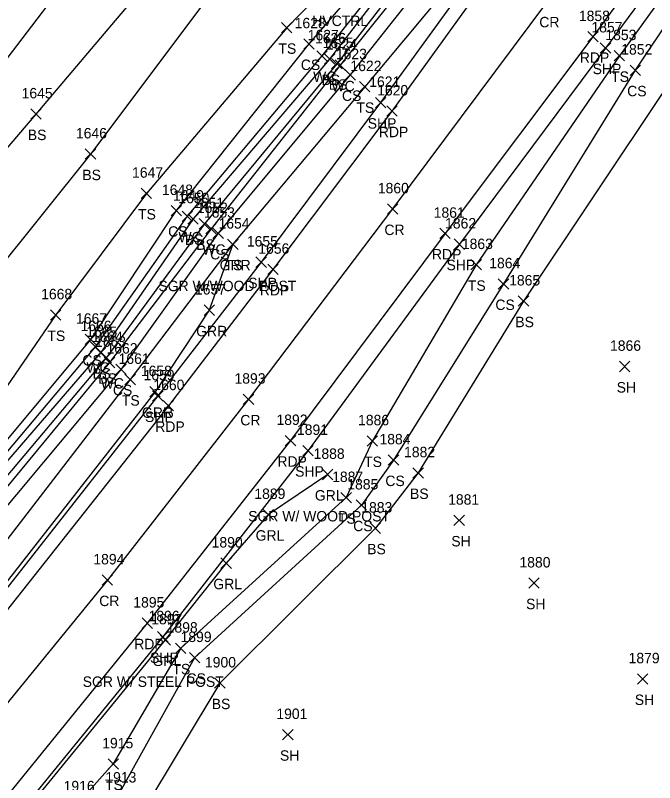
# Model space of a CAD drawing. Extents: x 1520648 to 1523413, y 732854 to 735518.
# Drawn here: x 1522267.9 to 1522390.5, y 733961.6 to 734108.7 of the extents above; entities that cross this region are included whole.
import ezdxf

# ---------------------------------------------------------------- set-up
doc = ezdxf.new("R2010")
doc.units = 0
for name, color, linetype in [('C_A', 7, 'Continuous'), ('D_I', 7, 'Continuous'), ('L_A', 7, 'Continuous'), ('L_I', 7, 'Continuous'), ('L_TIC', 7, 'Continuous'), ('LAWE', 7, 'Continuous'), ('LELB', 7, 'Continuous'), ('P_A', 7, 'Continuous'), ('P_I', 7, 'Continuous'), ('P_TIC', 7, 'Continuous'), ('PET', 7, 'Continuous'), ('PRC', 7, 'Continuous'), ('PSP', 7, 'Continuous'), ('R_A', 7, 'Continuous'), ('R_C', 7, 'Continuous'), ('R_I', 7, 'Continuous'), ('R_TIC', 7, 'Continuous'), ('RGR', 7, 'Continuous')]:
    doc.layers.add(name, color=color, linetype=linetype)

msp = doc.modelspace()

# ---------------------------------------------------------------- linework, layer by layer
at = {"layer": 'L_TIC'}
for points in [[(1522318.92, 734105.37), (1522320.92, 734107.37)], [(1522320.92, 734105.37), (1522318.92, 734107.37)], [(1522323.18, 734102.26), (1522325.18, 734104.26)], [(1522325.18, 734102.26), (1522323.18, 734104.26)], [(1522325.68, 734099.96), (1522327.68, 734101.96)], [(1522327.68, 734099.96), (1522325.68, 734101.96)], [(1522382.71, 734099.99), (1522384.71, 734101.99)], [(1522384.71, 734099.99), (1522382.71, 734101.99)], [(1522327.14, 734099.37), (1522329.14, 734101.37)], [(1522329.14, 734099.37), (1522327.14, 734101.37)], [(1522328.53, 734098.47), (1522330.53, 734100.47)], [(1522330.53, 734098.47), (1522328.53, 734100.47)], [(1522329.19, 734098.19), (1522331.19, 734100.19)], [(1522331.19, 734098.19), (1522329.19, 734100.19)], [(1522385.75, 734097.22), (1522387.75, 734099.22)], [(1522387.75, 734097.22), (1522385.75, 734099.22)], [(1522331.08, 734096.33), (1522333.08, 734098.33)], [(1522333.08, 734096.33), (1522331.08, 734098.33)], [(1522333.87, 734094.05), (1522335.87, 734096.05)], [(1522335.87, 734094.05), (1522333.87, 734096.05)], [(1522270.83, 734088.82), (1522272.83, 734090.82)], [(1522272.83, 734088.82), (1522270.83, 734090.82)], [(1522281.29, 734081.14), (1522283.29, 734083.14)], [(1522283.29, 734081.14), (1522281.29, 734083.14)], [(1522292, 734073.6), (1522294, 734075.6)], [(1522294, 734073.6), (1522292, 734075.6)], [(1522297.74, 734070.29), (1522299.74, 734072.29)], [(1522299.74, 734070.29), (1522297.74, 734072.29)], [(1522299.85, 734069.21), (1522301.85, 734071.21)], [(1522301.85, 734069.21), (1522299.85, 734071.21)], [(1522300.96, 734068.71), (1522302.96, 734070.71)], [(1522302.96, 734068.71), (1522300.96, 734070.71)], [(1522303.13, 734067.77), (1522305.13, 734069.77)], [(1522305.13, 734067.77), (1522303.13, 734069.77)], [(1522304.41, 734066.83), (1522306.41, 734068.83)], [(1522306.41, 734066.83), (1522304.41, 734068.83)], [(1522305.78, 734065.94), (1522307.78, 734067.94)], [(1522307.78, 734065.94), (1522305.78, 734067.94)], [(1522308.58, 734063.85), (1522310.58, 734065.85)], [(1522310.58, 734063.85), (1522308.58, 734065.85)], [(1522355.24, 734059.92), (1522357.24, 734061.92)], [(1522357.24, 734059.92), (1522355.24, 734061.92)], [(1522360.49, 734056.24), (1522362.49, 734058.24)], [(1522362.49, 734056.24), (1522360.49, 734058.24)], [(1522364.31, 734052.94), (1522366.31, 734054.94)], [(1522366.31, 734052.94), (1522364.31, 734054.94)], [(1522274.62, 734050.29), (1522276.62, 734052.29)], [(1522276.62, 734050.29), (1522274.62, 734052.29)], [(1522281.29, 734045.6), (1522283.29, 734047.6)], [(1522283.29, 734045.6), (1522281.29, 734047.6)], [(1522282.21, 734044.19), (1522284.21, 734046.19)], [(1522284.21, 734044.19), (1522282.21, 734046.19)], [(1522283.25, 734043.07), (1522285.25, 734045.07)], [(1522285.25, 734043.07), (1522283.25, 734045.07)], [(1522284.33, 734042.1), (1522286.33, 734044.1)], [(1522286.33, 734042.1), (1522284.33, 734044.1)], [(1522284.94, 734041.17), (1522286.94, 734043.17)], [(1522286.94, 734041.17), (1522284.94, 734043.17)], [(1522287.15, 734039.88), (1522289.15, 734041.88)], [(1522289.15, 734039.88), (1522287.15, 734041.88)], [(1522383.7, 734040.41), (1522385.7, 734042.41)], [(1522385.7, 734040.41), (1522383.7, 734042.41)], [(1522288.9, 734037.9), (1522290.9, 734039.9)], [(1522290.9, 734037.9), (1522288.9, 734039.9)], [(1522335.35, 734026.13), (1522337.35, 734028.13)], [(1522337.35, 734026.13), (1522335.35, 734028.13)], [(1522339.39, 734022.47), (1522341.39, 734024.47)], [(1522341.39, 734022.47), (1522339.39, 734024.47)], [(1522344.12, 734020), (1522346.12, 734022)], [(1522346.12, 734020), (1522344.12, 734022)], [(1522330.32, 734015.25), (1522332.32, 734017.25)], [(1522332.32, 734015.25), (1522330.32, 734017.25)], [(1522333.23, 734013.82), (1522335.23, 734015.82)], [(1522335.23, 734013.82), (1522333.23, 734015.82)], [(1522351.99, 734010.9), (1522353.99, 734012.9)], [(1522353.99, 734010.9), (1522351.99, 734012.9)], [(1522335.91, 734009.39), (1522337.91, 734011.39)], [(1522337.91, 734009.39), (1522335.91, 734011.39)], [(1522366.32, 733998.86), (1522368.32, 734000.86)], [(1522368.32, 733998.86), (1522366.32, 734000.86)], [(1522298.59, 733986.37), (1522300.59, 733988.37)], [(1522300.59, 733986.37), (1522298.59, 733988.37)], [(1522301.26, 733984.56), (1522303.26, 733986.56)], [(1522303.26, 733984.56), (1522301.26, 733986.56)], [(1522387.18, 733980.49), (1522389.18, 733982.49)], [(1522389.18, 733980.49), (1522387.18, 733982.49)], [(1522306.1, 733979.69), (1522308.1, 733981.69)], [(1522308.1, 733979.69), (1522306.1, 733981.69)], [(1522319.14, 733969.8), (1522321.14, 733971.8)], [(1522321.14, 733969.8), (1522319.14, 733971.8)], [(1522285.66, 733964.18), (1522287.66, 733966.18)], [(1522287.66, 733964.18), (1522285.66, 733966.18)]]:
    msp.add_lwpolyline(points, dxfattribs=at)
at = {"layer": 'LAWE'}
for points in [[(1522250.49, 734235.04), (1522272.42, 734218.93), (1522297.87, 734198.74), (1522307.58, 734174.2), (1522311.43, 734163.77), (1522313.95, 734156.23), (1522320.92, 734149.6), (1522331.75, 734145.28), (1522341.38, 734144.28), (1522344.65, 734145.3), (1522354.27, 734148.79), (1522359.63, 734149.42), (1522357.59, 734144.36), (1522350.28, 734130.69), (1522326.68, 734100.96), (1522300.85, 734070.21), (1522283.21, 734045.19), (1522247.83, 734003.16), (1522235.94, 733986.96), (1522232.5, 733982.11), (1522233.89, 733977.86), (1522237.92, 733975.08)], [(1522353.21, 734128.04), (1522330.19, 734099.19), (1522305.41, 734067.83), (1522285.94, 734042.17), (1522251.34, 734000.27), (1522241.39, 733985.1), (1522240.93, 733982.18), (1522242.68, 733979.91)]]:
    msp.add_lwpolyline(points, dxfattribs=at)
at = {"layer": 'LELB'}
for points in [[(1522457.97, 734316.51), (1522465.36, 734303.49), (1522470.91, 734292.36), (1522471.73, 734284.06), (1522466.06, 734271.74), (1522460.87, 734262.7), (1522429.3, 734219.62), (1522405.44, 734187.85), (1522380.78, 734154.69), (1522358.58, 734123.49), (1522334.87, 734095.05), (1522309.58, 734064.85), (1522289.9, 734038.9), (1522256.58, 733995.71), (1522247.93, 733981.24), (1522246.39, 733977.74)], [(1522251.12, 734236.06), (1522272.79, 734219.75), (1522299.13, 734200.04), (1522308.73, 734174.59), (1522312.88, 734163.82), (1522314.78, 734156.55), (1522320.99, 734151.62), (1522332.23, 734147.49), (1522341.11, 734146.75), (1522344.98, 734146), (1522353.74, 734149.87), (1522359.96, 734152.11), (1522361.65, 734150.34), (1522359.01, 734144.16), (1522350.93, 734130.05), (1522328.14, 734100.37), (1522301.96, 734069.71), (1522284.25, 734044.07), (1522248.49, 734002.65), (1522236.85, 733986.42), (1522234.99, 733978.89), (1522237.8, 733975.96)], [(1522244.93, 734228.52), (1522263.32, 734209.37), (1522289.49, 734189.74), (1522306.79, 734166.34), (1522312.53, 734155.32), (1522317.63, 734143.65), (1522298.72, 734121.6), (1522271.83, 734089.82), (1522252.2, 734066.84), (1522225.77, 734033.34), (1522220.1, 734019.64), (1522210.97, 733988.14), (1522200.09, 733970.45)], [(1522237.38, 734218.53), (1522258.22, 734200.84), (1522283.25, 734181.69), (1522301.32, 734163.17), (1522304.68, 734146.8), (1522288.26, 734129.35), (1522261.48, 734094.25), (1522252.67, 734080.33), (1522245.86, 734070.77), (1522213.93, 734029.6), (1522209.42, 734024), (1522201.64, 733983.59), (1522200.09, 733970.45), (1522202, 733964.19)], [(1522376.81, 734157.78), (1522371.61, 734153.22), (1522364.35, 734141.54), (1522355.25, 734126.63), (1522332.08, 734097.33), (1522306.78, 734066.94), (1522288.15, 734040.88), (1522253.17, 733999.02), (1522246.65, 733983.97), (1522243.7, 733979.27)], [(1522344.65, 734145.3), (1522347.17, 734143.46), (1522354.53, 734146.44), (1522357.59, 734144.36), (1522349.22, 734132.39), (1522324.18, 734103.26), (1522298.74, 734071.29), (1522282.29, 734046.6), (1522246.81, 734004.08), (1522231.67, 733985.08), (1522222.7, 733979.34)], [(1522331.75, 734145.28), (1522330.83, 734143.25), (1522307.65, 734116.03), (1522282.29, 734082.14), (1522263.45, 734058.68), (1522234.48, 734027.83), (1522226.55, 734014.57), (1522216.68, 733985.08), (1522202, 733964.19)], [(1522353.25, 734140.58), (1522319.92, 734106.37), (1522293, 734074.6), (1522275.62, 734051.29), (1522244.54, 734005.97), (1522222.7, 733979.34), (1522202, 733964.19), (1522167.92, 733938.99), (1522145.37, 733925.91), (1522137.65, 733917.42), (1522137.34, 733905.34), (1522137.09, 733900.6)], [(1522352.2, 734128.76), (1522329.53, 734099.47), (1522304.13, 734068.77), (1522285.33, 734043.1), (1522250.23, 734001.4), (1522240.08, 733985.46), (1522239.34, 733981.94), (1522242.19, 733979.33), (1522245.31, 733977.41), (1522241.67, 733973.03), (1522239.46, 733974.66), (1522237.8, 733975.96)], [(1522399.21, 734122.54), (1522383.71, 734100.99), (1522356.24, 734060.92), (1522336.35, 734027.13), (1522331.32, 734016.25), (1522299.59, 733987.37), (1522286.66, 733965.18), (1522279.32, 733956.93)], [(1522401.8, 734120.85), (1522386.75, 734098.22), (1522361.49, 734057.24), (1522340.39, 734023.47), (1522334.23, 734014.82), (1522302.26, 733985.56), (1522287.26, 733958.62), (1522280.22, 733955.73), (1522278.18, 733953.83)], [(1522392.7, 734094.89), (1522365.31, 734053.94), (1522345.12, 734021), (1522336.91, 734010.39), (1522307.1, 733980.69), (1522292.25, 733956), (1522286.28, 733952.54), (1522279.05, 733951.64), (1522278.18, 733953.83), (1522276.92, 733952.03)]]:
    msp.add_lwpolyline(points, dxfattribs=at)
at = {"layer": 'P_TIC'}
for points in [[(1522377.63, 734103.64), (1522379.63, 734105.64)], [(1522379.63, 734103.64), (1522377.63, 734105.64)], [(1522380.04, 734101.47), (1522382.04, 734103.47)], [(1522382.04, 734101.47), (1522380.04, 734103.47)], [(1522336.92, 734091.02), (1522338.92, 734093.02)], [(1522338.92, 734091.02), (1522336.92, 734093.02)], [(1522339.09, 734089.38), (1522341.09, 734091.38)], [(1522341.09, 734089.38), (1522339.09, 734091.38)], [(1522339.21, 734070.61), (1522341.21, 734072.61)], [(1522341.21, 734070.61), (1522339.21, 734072.61)], [(1522349.27, 734065.93), (1522351.27, 734067.93)], [(1522351.27, 734065.93), (1522349.27, 734067.93)], [(1522352.02, 734063.87), (1522354.02, 734065.87)], [(1522354.02, 734063.87), (1522352.02, 734065.87)], [(1522314.01, 734060.41), (1522316.01, 734062.41)], [(1522316.01, 734060.41), (1522314.01, 734062.41)], [(1522316.27, 734059.02), (1522318.27, 734061.02)], [(1522318.27, 734059.02), (1522316.27, 734061.02)], [(1522294.21, 734034.76), (1522296.21, 734036.76)], [(1522296.21, 734034.76), (1522294.21, 734036.76)], [(1522311.59, 734034.11), (1522313.59, 734036.11)], [(1522313.59, 734034.11), (1522311.59, 734036.11)], [(1522296.22, 734032.87), (1522298.22, 734034.87)], [(1522298.22, 734032.87), (1522296.22, 734034.87)], [(1522319.64, 734026.19), (1522321.64, 734028.19)], [(1522321.64, 734026.19), (1522319.64, 734028.19)], [(1522323.01, 734024.28), (1522325.01, 734026.28)], [(1522325.01, 734024.28), (1522323.01, 734026.28)], [(1522284.54, 733999.45), (1522286.54, 734001.45)], [(1522286.54, 733999.45), (1522284.54, 734001.45)], [(1522292.19, 733991.18), (1522294.19, 733993.18)], [(1522294.19, 733991.18), (1522292.19, 733993.18)], [(1522295.17, 733988.55), (1522297.17, 733990.55)], [(1522297.17, 733988.55), (1522295.17, 733990.55)]]:
    msp.add_lwpolyline(points, dxfattribs=at)
at = {"layer": 'PET'}
for points in [[(1522409.89, 734185.46), (1522384.8, 734151.86), (1522362.15, 734120.96), (1522340.09, 734090.38), (1522317.27, 734060.02), (1522297.22, 734033.87), (1522262.69, 733990.17), (1522247.44, 733972.23), (1522223.91, 733946.24), (1522192.48, 733913.96), (1522164.52, 733888.05), (1522124.7, 733855.72), (1522089.98, 733831.33), (1522050.33, 733806.1), (1522008.23, 733782.16), (1521961.73, 733759.37), (1521937.85, 733748.92), (1521892.74, 733731.02), (1521853.04, 733716.93), (1521810.12, 733704.13), (1521784.9, 733696.8), (1521738.04, 733684.33), (1521683.5, 733669.74)], [(1522405.75, 734141.77), (1522378.63, 734104.64), (1522350.27, 734066.93), (1522320.64, 734027.19), (1522293.19, 733992.18), (1522263.71, 733955.95)]]:
    msp.add_lwpolyline(points, dxfattribs=at)
at = {"layer": 'PRC'}
msp.add_lwpolyline([(1522396.73, 734148.57), (1522369.92, 734111.45), (1522340.21, 734071.61), (1522312.59, 734035.11), (1522285.54, 734000.45), (1522254.71, 733962.62), (1522224.2, 733929)], dxfattribs=at)
at = {"layer": 'PSP'}
for points in [[(1522407.44, 734186.96), (1522382.7, 734153.4), (1522359.98, 734122.45), (1522337.92, 734092.02), (1522315.01, 734061.41), (1522295.21, 734035.76), (1522260.62, 733991.79), (1522245.88, 733973.99), (1522222.05, 733948.06), (1522190.45, 733915.42), (1522160.99, 733888.49), (1522154.25, 733883.34), (1522127.34, 733861.55), (1522088.3, 733833.58), (1522048.98, 733808.78), (1522007.27, 733785.06), (1521960.9, 733762.47), (1521936.68, 733751.08), (1521891.96, 733733.48), (1521851.86, 733719.56), (1521809.02, 733706.62), (1521784.1, 733699.99), (1521736.06, 733688.52), (1521682.58, 733672.91)], [(1522408.2, 734139.28), (1522381.04, 734102.47), (1522353.02, 734064.87), (1522324.01, 734025.28), (1522296.17, 733989.55), (1522266.63, 733953.31), (1522235.29, 733918.79), (1522209.78, 733890.98), (1522201.9, 733884.12), (1522173.49, 733859.11), (1522154.03, 733843.41), (1522113.55, 733816.07), (1522079.34, 733793.19), (1522048.3, 733774.46), (1522016.59, 733757.42), (1521993.94, 733745.83), (1521965.16, 733732.44), (1521948.66, 733724.97), (1521904.28, 733707.61), (1521888.63, 733701.99), (1521847.29, 733686.72), (1521809.29, 733673.67)]]:
    msp.add_lwpolyline(points, dxfattribs=at)
at = {"layer": 'R_TIC'}
for points in [[(1522308.58, 734063.85), (1522310.58, 734065.85)], [(1522310.58, 734063.85), (1522308.58, 734065.85)], [(1522304.06, 734051.2), (1522306.06, 734053.2)], [(1522306.06, 734051.2), (1522304.06, 734053.2)], [(1522293.68, 734035.56), (1522295.68, 734037.56)], [(1522295.68, 734035.56), (1522293.68, 734037.56)], [(1522326.77, 734019.69), (1522328.77, 734021.69)], [(1522328.77, 734019.69), (1522326.77, 734021.69)], [(1522315.41, 734012), (1522317.41, 734014)], [(1522317.41, 734012), (1522315.41, 734014)], [(1522307.3, 734002.69), (1522309.3, 734004.69)], [(1522309.3, 734002.69), (1522307.3, 734004.69)], [(1522295.64, 733987.96), (1522297.64, 733989.96)], [(1522297.64, 733987.96), (1522295.64, 733989.96)]]:
    msp.add_lwpolyline(points, dxfattribs=at)
at = {"layer": 'RGR'}
for points in [[(1522309.58, 734064.85), (1522305.06, 734052.2), (1522294.68, 734036.56), (1522260.13, 733992.38), (1522248.03, 733977.91), (1522242.5, 733971.47), (1522221.51, 733948.35), (1522189.83, 733915.76), (1522160.34, 733889.29), (1522154.71, 733885.83), (1522148.5, 733886.44)], [(1522327.77, 734020.69), (1522316.41, 734013), (1522308.3, 734003.69), (1522296.64, 733988.96), (1522267.17, 733952.95), (1522235.76, 733918.25), (1522219.05, 733899.75), (1522212.83, 733888.73)]]:
    msp.add_lwpolyline(points, dxfattribs=at)

# ---------------------------------------------------------------- texts
at = {"layer": 'C_A'}
msp.add_text('HVCTRL', height=2, dxfattribs=at).set_placement((1522324.83, 734106.69))
at = {"layer": 'D_I'}
msp.add_text('1916', height=2, dxfattribs=at).set_placement((1522277.14, 733959.93))
at = {"layer": 'L_A'}
for s, p in [('TS', (1522318.33, 734101.37)), ('CS', (1522322.62, 734098.26)), ('WC', (1522324.98, 734095.96)), ('BS', (1522326.58, 734095.37)), ('TS', (1522382.12, 734095.99)), ('BS', (1522327.97, 734094.47)), ('WC', (1522328.5, 734094.19)), ('CS', (1522330.52, 734092.33)), ('CS', (1522385.2, 734093.22)), ('TS', (1522333.28, 734090.05)), ('BS', (1522270.27, 734084.82)), ('BS', (1522280.73, 734077.14)), ('TS', (1522291.41, 734069.6)), ('CS', (1522297.18, 734066.29)), ('WC', (1522299.16, 734065.21)), ('BS', (1522300.4, 734064.71)), ('BS', (1522302.57, 734063.77)), ('WC', (1522303.72, 734062.83)), ('CS', (1522305.22, 734061.94)), ('TS', (1522307.99, 734059.85)), ('TS', (1522354.65, 734055.92)), ('CS', (1522359.93, 734052.24)), ('BS', (1522363.75, 734048.94)), ('TS', (1522274.03, 734046.29)), ('CS', (1522280.73, 734041.6)), ('WC', (1522281.52, 734040.19)), ('BS', (1522282.69, 734039.07)), ('BS', (1522283.77, 734038.1)), ('WC', (1522284.25, 734037.17)), ('SH', (1522383.19, 734036.41)), ('CS', (1522286.59, 734035.88)), ('TS', (1522288.31, 734033.9)), ('TS', (1522334.76, 734022.13)), ('CS', (1522338.83, 734018.47)), ('BS', (1522343.56, 734016)), ('TS', (1522329.73, 734011.25)), ('CS', (1522332.67, 734009.82)), ('SH', (1522351.48, 734006.9)), ('BS', (1522335.35, 734005.39)), ('SH', (1522365.81, 733994.86)), ('TS', (1522298, 733982.37)), ('CS', (1522300.71, 733980.56)), ('SH', (1522386.66, 733976.49)), ('BS', (1522305.54, 733975.69)), ('SH', (1522318.62, 733965.8)), ('TS', (1522285.07, 733960.18))]:
    msp.add_text(s, height=2, dxfattribs=at).set_placement(p)
at = {"layer": 'L_I'}
for s, p in [('1628', (1522321.44, 734106.26)), ('1627', (1522323.94, 734103.96)), ('1853', (1522381.02, 734103.99)), ('1626', (1522325.34, 734103.37)), ('1625', (1522326.79, 734102.47)), ('1624', (1522327.45, 734102.19)), ('1852', (1522384.06, 734101.22)), ('1623', (1522329.34, 734100.33)), ('1622', (1522332.13, 734098.05)), ('1645', (1522269.09, 734092.82)), ('1646', (1522279.5, 734085.14)), ('1647', (1522290.26, 734077.6)), ('1648', (1522296, 734074.29)), ('1649', (1522298.1, 734073.21)), ('1650', (1522299.13, 734072.71)), ('1651', (1522301.95, 734071.77)), ('1652', (1522302.67, 734070.83)), ('1653', (1522304.04, 734069.94)), ('1654', (1522306.84, 734067.85)), ('1863', (1522353.5, 734063.92)), ('1864', (1522358.75, 734060.24)), ('1865', (1522362.57, 734056.94)), ('1668', (1522272.83, 734054.29)), ('1667', (1522279.51, 734049.6)), ('1666', (1522280.37, 734048.19)), ('1665', (1522281.47, 734047.07)), ('1664', (1522282.55, 734046.1)), ('1663', (1522283.16, 734045.17)), ('1662', (1522285.36, 734043.88)), ('1866', (1522381.91, 734044.41)), ('1661', (1522287.68, 734041.9)), ('1886', (1522333.6, 734030.13)), ('1884', (1522337.7, 734026.47)), ('1882', (1522342.42, 734024)), ('1887', (1522328.63, 734019.25)), ('1885', (1522331.53, 734017.82)), ('1881', (1522350.87, 734014.9)), ('1883', (1522334.21, 734013.39)), ('1880', (1522364.54, 734002.86)), ('1898', (1522296.9, 733990.37)), ('1899', (1522299.56, 733988.56)), ('1900', (1522304.24, 733983.69)), ('1879', (1522385.47, 733984.49)), ('1901', (1522317.93, 733973.8)), ('1915', (1522284.54, 733968.18)), ('1913', (1522285.14, 733961.62)), ('1916', (1522277.14, 733959.93))]:
    msp.add_text(s, height=2, dxfattribs=at).set_placement(p)
at = {"layer": 'P_A'}
for s, p in [('CR', (1522368.35, 734106.45)), ('RDP', (1522376.12, 734099.64)), ('SHP', (1522378.58, 734097.47)), ('SHP', (1522335.45, 734087.02)), ('RDP', (1522337.58, 734085.38)), ('CR', (1522338.65, 734066.61)), ('RDP', (1522347.76, 734061.93)), ('SHP', (1522350.56, 734059.87)), ('SHP', (1522312.54, 734056.41)), ('RDP', (1522314.76, 734055.02)), ('SHP', (1522292.75, 734030.76)), ('RDP', (1522294.71, 734028.87)), ('CR', (1522311.02, 734030.11)), ('RDP', (1522318.13, 734022.19)), ('SHP', (1522321.54, 734020.28)), ('CR', (1522283.97, 733995.45)), ('RDP', (1522290.68, 733987.18)), ('SHP', (1522293.71, 733984.55))]:
    msp.add_text(s, height=2, dxfattribs=at).set_placement(p)
at = {"layer": 'P_I'}
for s, p in [('1858', (1522375.94, 734107.64)), ('1857', (1522378.35, 734105.47)), ('1621', (1522335.74, 734095.02)), ('1620', (1522337.26, 734093.38)), ('1860', (1522337.39, 734074.61)), ('1861', (1522348.1, 734069.93)), ('1862', (1522350.28, 734067.87)), ('1655', (1522312.27, 734064.41)), ('1656', (1522314.47, 734063.02)), ('1659', (1522292.47, 734038.76)), ('1893', (1522309.9, 734038.11)), ('1660', (1522294.35, 734036.87)), ('1892', (1522317.95, 734030.19)), ('1891', (1522321.88, 734028.28)), ('1894', (1522282.84, 734003.45)), ('1895', (1522290.5, 733995.18)), ('1896', (1522293.43, 733992.55))]:
    msp.add_text(s, height=2, dxfattribs=at).set_placement(p)
at = {"layer": 'R_A'}
for s, p in [('GRR', (1522307.06, 734059.85)), ('GRR', (1522302.55, 734047.2)), ('GRR', (1522292.17, 734031.56)), ('GRL', (1522325.31, 734015.69)), ('GRL', (1522313.96, 734008)), ('GRL', (1522305.85, 733998.69)), ('GRL', (1522294.18, 733983.96))]:
    msp.add_text(s, height=2, dxfattribs=at).set_placement(p)
at = {"layer": 'R_C'}
for s, p in [('SGR W/WOOD POST', (1522295.32, 734055.85)), ('SGR W/ WOOD POST', (1522312.53, 734011.69)), ('SGR W/ STEEL POST', (1522280.8, 733979.96))]:
    msp.add_text(s, height=2, dxfattribs=at).set_placement(p)
at = {"layer": 'R_I'}
for s, p in [('1654', (1522306.84, 734067.85)), ('1657', (1522302.32, 734055.2)), ('1658', (1522291.94, 734039.56)), ('1888', (1522325.08, 734023.69)), ('1889', (1522313.71, 734016)), ('1890', (1522305.52, 734006.69)), ('1897', (1522293.94, 733991.96))]:
    msp.add_text(s, height=2, dxfattribs=at).set_placement(p)

doc.saveas('drawing.dxf')
